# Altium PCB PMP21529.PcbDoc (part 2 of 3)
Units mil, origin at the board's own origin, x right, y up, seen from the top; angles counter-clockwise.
Board outline 4400 x 2200 mil, 4 copper layers (Top Layer, Signal Layer 1, Signal Layer 2, Bottom Layer), stack 41.2 mil thick; 196 components, 92 nets, 502 pads, 268 vias.
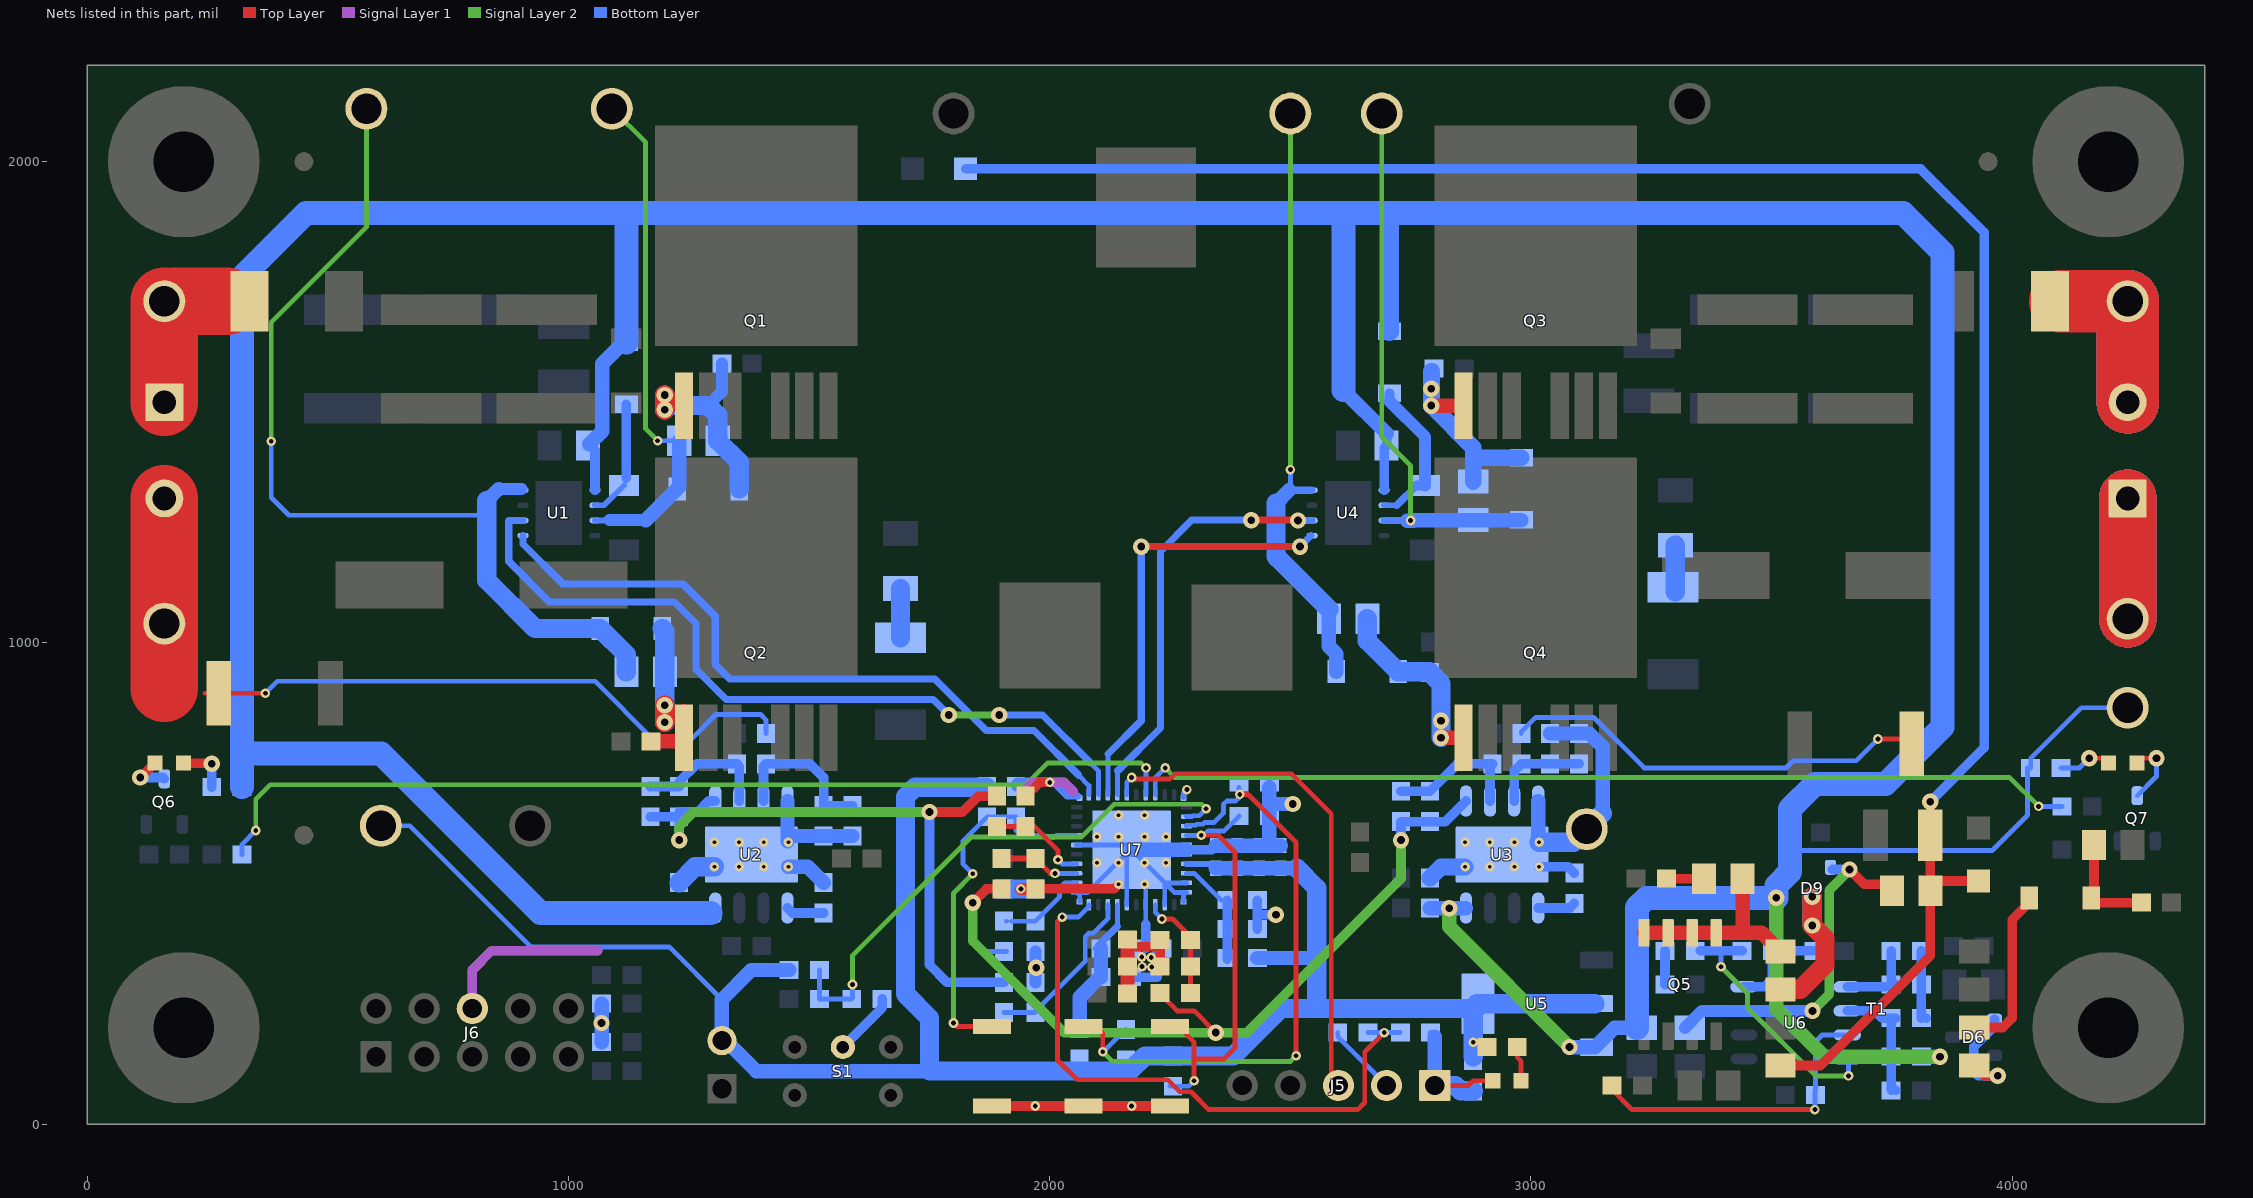
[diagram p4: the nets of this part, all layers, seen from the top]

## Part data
C1 C2 C3 C4 C5 C6 C7 C8: library part CMP-0009304-2, "CAP, CERM, 10 uF, 100 V, +/- 20%, X7R, 2220", Cap_Case=2220, Manufacturer=AVX, Supplier Part Number 1=478-9622-1-ND, TempCo=X7R, Tolerance_%=20%, Value1=Unknown, Value2=100V, ValueDisplayed=10uF
C9 C10: library part CMP-0011230-3, "CAP, AL, 100 uF, 100 V, +/- 20%, SMD", Cap_Case=KE0, Manufacturer=Chemi-Con, Tolerance_%=20%, Value1=Unknown, Value2=100V, ValueDisplayed=100uF
C11 C12: library part CMP-0007427-4, "CAP, CERM, 6800 pF, 25 V, +/- 10%, X7R, 0603", Cap_Case=0603, Manufacturer=MuRata, Supplier Part Number 1=81-GRM18R71E682KA01D, TempCo=X7R, Tolerance_%=10%, Value1=Unknown, Value2=25V, ValueDisplayed=6800pF
C13 C14 C21 C24 C27 C28: library part CMP-0006775-4, "CAP, CERM, 22 pF, 50 V, +/- 5%, C0G/NP0, 0603", Cap_Case=0603, Manufacturer=AVX, PartNumber=06035A220JAT2A, Supplier Part Number 1=478-1167-1-ND, TempCo=C0G/NP0, Tolerance_%=5%, Value1="0.259 ohm", Value2=50V, ValueDisplayed=22pF
C15 C16: library part CMP-0006752-5, "CAP, CERM, 0.1 uF, 25 V, +/- 5%, X7R, 0603", Cap_Case=0603, Manufacturer=AVX, PartNumber=06033C104JAT2A, Supplier Part Number 1=478-3713-1-ND, TempCo=X7R, Tolerance_%=5%, Value1="0.05 ohm", Value2=25V, ValueDisplayed=0.1uF
C17 C18: library part CMP-0006784-4, "CAP, CERM, 330 pF, 50 V, +/- 5%, C0G/NP0, 0603", Cap_Case=0603, Manufacturer=AVX, PartNumber=06035A331JAT2A, Supplier Part Number 1=478-1181-1-ND, TempCo=C0G/NP0, Tolerance_%=5%, Value1="0.071 ohm", Value2=50V, ValueDisplayed=330pF
C19 C29: library part CMP-0008334-2, "CAP, CERM, 4.7 uF, 16 V, +/- 10%, X7R, 0805", Cap_Case=0805, Manufacturer=MuRata, Supplier Part Number 1=490-4522-1-ND, TempCo=X7R, Tolerance_%=10%, Value1="0.006 ohm", Value2=16V, ValueDisplayed=4.7uF
C20 C22 C51: library part CMP-0006906-5, "CAP, CERM, 2.2 uF, 10 V, +/- 10%, X5R, 0603", Cap_Case=0603, Manufacturer=Kemet, PartNumber=C0603C225K8PACTU, Supplier Part Number 1=399-4911-1-ND, TempCo=X5R, Tolerance_%=10%, Value1=Unknown, Value2=10V, ValueDisplayed=2.2uF
C23 C30: library part CMP-0008724-2, "CAP, CERM, 2.2 uF, 100 V, +/- 10%, X7S, 1206", Cap_Case=1206_180, Manufacturer=TDK, Supplier Part Number 1=445-5207-1-ND, TempCo=X7S, Tolerance_%=10%, Value1="0.005718 ohm", Value2=100V, ValueDisplayed=2.2uF
C25 C66: library part CMP-0006895-4, "CAP, CERM, 220 pF, 50 V, +/- 10%, X7R, 0603", Cap_Case=0603, Manufacturer=Kemet, Supplier Part Number 1=399-1071-1-ND, TempCo=X7R, Tolerance_%=10%, Value1=Unknown, Value2=50V, ValueDisplayed=220pF
C26 C40 C47 C60: library part CMP-0006726-4, "CAP, CERM, 0.01 uF, 100 V, +/- 5%, X7R, 0603", Cap_Case=0603, Manufacturer=AVX, PartNumber=06031C103JAT2A, Supplier Part Number 1=478-3700-1-ND, TempCo=X7R, Tolerance_%=5%, Value1="0.098 ohm", Value2=100V, ValueDisplayed=0.01uF
C31 C34: library part CMP-0007770-2, "CAP, CERM, 2.2 uF, 16 V, +/- 10%, X7R, 0805", Cap_Case=0805, Manufacturer=Kemet, PartNumber=C0805C225K4RACTU, Supplier Part Number 1=399-3523-1-ND, TempCo=X7R, Tolerance_%=10%, Value1="0.008 ohm", Value2=16V, ValueDisplayed=2.2uF
C32: library part CMP-0007828-2, "CAP, CERM, 10 uF, 25 V, +/- 10%, X5R, 0805", Cap_Case=0805, Manufacturer=TDK, PartNumber=C2012X5R1E106K125AB, Supplier Part Number 1=445-5984-1-ND, TempCo=X5R, Tolerance_%=10%, Value1=Unknown, Value2=25V, ValueDisplayed=10uF
C33: library part CMP-0006872-5, "CAP, CERM, 10 uF, 6.3 V, +/- 20%, X5R, 0603", Cap_Case=0603, Manufacturer=Kemet, PartNumber=C0603C106M9PACTU, Supplier Part Number 1=399-5504-1-ND, TempCo=X5R, Tolerance_%=20%, Value1="0.004 ohm", Value2=6.3V, ValueDisplayed=10uF
C35: library part CMP-0009232-2, "CAP, CERM, 2.2 uF, 100 V, +/- 10%, X7R, 1210", Cap_Case=1210, Manufacturer=MuRata, Supplier Part Number 1=490-3385-1-ND, TempCo=X7R, Tolerance_%=10%, Value1="0.007 ohm", Value2=100V, ValueDisplayed=2.2uF
C36: library part CMP-0006854-4, "CAP, CERM, 0.01 uF, 50 V, +/- 10%, X7R, 0603", Cap_Case=0603, Manufacturer=Kemet, PartNumber=C0603C103K5RACTU, Supplier Part Number 1=399-1091-1-ND, TempCo=X7R, Tolerance_%=10%, Value1=Unknown, Value2=50V, ValueDisplayed=0.01uF
C37 C52: library part CMP-0007120-4, "CAP, CERM, 1 uF, 16 V, +/- 10%, X7R, 0603", Cap_Case=0603, Manufacturer="Taiyo Yuden", Supplier Part Number 1=1683647, TempCo=X7R, Tolerance_%=10%, Value1=Unknown, Value2=16V, ValueDisplayed=1uF
C38: library part CMP-0008244-2, "CAP, CERM, 47 pF, 250 V, +/- 5%, C0G/NP0, 0805", Cap_Case=0805, Manufacturer=MuRata, PartNumber=GRM21A5C2E470JW01D, Supplier Part Number 1=490-5538-1-ND, TempCo=C0G/NP0, Tolerance_%=5%, Value1=Unknown, Value2=250V, ValueDisplayed=47pF
C39: library part CMP-0006789-4, "CAP, CERM, 47 pF, 50 V, +/- 5%, C0G/NP0, 0603", Cap_Case=0603, Manufacturer=AVX, PartNumber=06035A470JAT2A, Supplier Part Number 1=478-1171-1-ND, TempCo=C0G/NP0, Tolerance_%=5%, Value1="0.174 ohm", Value2=50V, ValueDisplayed=47pF
C41: library part CMP-0006868-5, "CAP, CERM, 1 uF, 16 V, +/- 10%, X5R, 0603", Cap_Case=0603, Manufacturer=Kemet, PartNumber=C0603C105K4PACTU, Supplier Part Number 1=399-5090-1-ND, TempCo=X5R, Tolerance_%=10%, Value1=Unknown, Value2=16V, ValueDisplayed=1uF
C42 C43 C44: library part CMP-0006659-2, "CAP, CERM, 0.1 uF, 25 V, +/- 10%, X7R, 0402", Cap_Case=0402, Manufacturer=MuRata, Supplier Part Number 1=490-10698-1-ND, TempCo=X7R, Tolerance_%=10%, Value1=Unknown, Value2=25V, ValueDisplayed=0.1uF
C45: library part CMP-0064947-2, "CAP, CERM, 1 uF, 6.3 V,+/- 10%, X7R, 0402", Cap_Case=0402, Manufacturer=MuRata, Supplier Part Number 1=490-10024-1-ND, TempCo=X7R, Tolerance_%=10%, Value1=Unknown, Value2=6.3V, ValueDisplayed=1uF
C46: library part CMP-0006921-4, "CAP, CERM, 330 pF, 50 V, +/- 10%, X7R, 0603", Cap_Case=0603, Manufacturer=Kemet, PartNumber=C0603C331K5RACTU, Supplier Part Number 1=399-1073-1-ND, TempCo=X7R, Tolerance_%=10%, Value1=Unknown, Value2=50V, ValueDisplayed=330pF
C48: library part CMP-0006802-4, "CAP, CERM, 0.1 uF, 50 V, +/- 10%, X7R, 0603", Cap_Case=0603, Manufacturer=AVX, PartNumber=06035C104KAT2A, Supplier Part Number 1=478-5052-1-ND, TempCo=X7R, Tolerance_%=10%, Value1=Unknown, Value2=50V, ValueDisplayed=0.1uF
C49: library part CMP-0006895-4, "CAP, CERM, 220 pF, 50 V, +/- 10%, X7R, 0603", Cap_Case=0603, Manufacturer=Kemet, PartNumber=C0603C221K5RACTU, Supplier Part Number 1=399-1071-1-ND, TempCo=X7R, Tolerance_%=10%, Value1=Unknown, Value2=50V, ValueDisplayed=220pF
C50: library part CMP-0008334-2, "CAP, CERM, 4.7 uF, 16 V, +/- 10%, X7R, 0805", Cap_Case=0805, Manufacturer=MuRata, PartNumber=GRM21BR71C475KA73L, Supplier Part Number 1=490-4522-1-ND, TempCo=X7R, Tolerance_%=10%, Value1="0.006 ohm", Value2=16V, ValueDisplayed=4.7uF
C53: library part CMP-0006975-4, "CAP, CERM, 0.01 uF, 25 V, +/- 5%, C0G/NP0, 0603", Cap_Case=0603, Manufacturer=Kemet, Supplier Part Number 1=399-5779-1-ND, TempCo=C0G/NP0, Tolerance_%=5%, Value1=Unknown, Value2=25V, ValueDisplayed=0.01uF
C54 C56 C57: library part CMP-0064934-4, "CAP, CERM, 2.2 uF, 16 V,+/- 10%, X7R, 0603", Cap_Case=0603, Manufacturer="Taiyo Yuden", Supplier Part Number 1=587-4864-1-ND, TempCo=X7R, Tolerance_%=10%, Value1=Unknown, Value2=16V, ValueDisplayed=2.2uF
C55 C59: library part CMP-0006722-4, "CAP, CERM, 33 pF, 100 V, +/- 5%, C0G/NP0, 0603", Cap_Case=0603, Manufacturer=AVX, PartNumber=06031A330JAT2A, Supplier Part Number 1=478-1143-1-ND, TempCo=C0G/NP0, Tolerance_%=5%, Value1="0.209 ohm", Value2=100V, ValueDisplayed=33pF
C58 C64: library part CMP-0009182-2, "CAP, CERM, 4.7 uF, 100 V, +/- 10%, X7S, 1210", Cap_Case=1210, Manufacturer=MuRata, Supplier Part Number 1=81-GRM32DC72A475KE1L, TempCo=X7S, Tolerance_%=10%, Value1=Unknown, Value2=100V, ValueDisplayed=4.7uF
C61 C65: library part CMP-0008710-2, "CAP, CERM, 1 uF, 100 V, +/- 10%, X7R, 1206", Cap_Case=1206_180, Manufacturer=TDK, Supplier Part Number 1=445-4467-1-ND, TempCo=X7R, Tolerance_%=10%, Value1="0.004575 ohm", Value2=100V, ValueDisplayed=1uF
C62 C63: library part CMP-0008852-2, "CAP, CERM, 5600 pF, 100 V, +/- 5%, C0G/NP0, 1206", Cap_Case=1206, Manufacturer=MuRata, Supplier Part Number 1=490-3353-1-ND, TempCo=C0G/NP0, Tolerance_%=5%, Value1="0.005 ohm", Value2=100V, ValueDisplayed=5600pF
D1 D2 D3 D4: library part CMP-0028526-1, "Diode, Schottky, 40 V, 0.5 A, SOD-123", Manufacturer="ON Semiconductor", Supplier Part Number 1=MBR0540T1GOSCT-ND, Value1=0.5A, Value2=0.51V
D5 D7: library part CMP-0028782-1, "Diode, Schottky, 100 V, 1 A, AEC-Q101, SOD-123W", Manufacturer=Nexperia, Supplier Part Number 1=568-12693-1-ND, Value1=1A, Value2=0.77V
D6: library part CMP-0076887-1, "Diode, P-N, 100 V, 0.2 A, SOT-23", Manufacturer="Fairchild Semiconductor", PartNumber=MMBD914, Supplier Part Number 1=MMBD914FSCT-ND, Value1=0.2A, Value2=0.95V
D8: library part CMP-0028548-1, "Diode, Schottky, 40 V, 1 A, SOD-123FL", Manufacturer="ON Semiconductor", Supplier Part Number 1=MBR140SFT1GOSCT-ND, Value1=1A, Value2=0.55V
D9: library part CMP-0076885-1, "Diode, Switching, 70 V, 0.25 A, SOT-23", Manufacturer=Vishay-Semiconductor, PartNumber=BAW56-V-GS08, Supplier Part Number 1=BAW56-V-GS08CT-ND, Value1=0.25A, Value2=0V
D10 D11 D12: library part CMP-0002827-2, "LED, Green, SMD", Color=green, Manufacturer=Lite-On, Power_TotalModule=100mW, Supplier Part Number 1=160-1183-1-ND, Value1=0.1W, Value2=2.1V
D13 D14: library part CMP-0028625-1, "Diode, Schottky, 100 V, 1 A, SOD-123FL", Manufacturer="ON Semiconductor", Supplier Part Number 1=MBR1H100SFT3GOSCT-ND, Value1=1A, Value2=0.76V
F1 F2: library part CMP-0003604-2, "Fuse, 15 A, SMD", Irating_A=15A, Manufacturer="Bel Fuse", Supplier Part Number 1=507-1059-1-ND
FID1 FID2 FID3: library part CMP-0077181-1, "Fiducial mark.  There is nothing to buy or mount.", Manufacturer=N/A
H1 H2 H3 H4: library part CMP-0003617-1, "Machine Screw, Round, #4-40 x 1/4, Nylon, Philips panhead", Manufacturer="B&F Fastener Supply", Supplier Part Number 1=H542-ND
H5 H6 H7 H8: library part CMP-0003610-1, "Standoff, Hex, 0.5\"L #4-40 Nylon", Manufacturer=Keystone, Supplier Part Number 1=36-1902C-ND
J1 J3: library part CMP-0074910-1, "Terminal Block, 5.08 mm, 2x1, Brass, TH", Color=Blue, Current_A=15A, Manufacturer="On-Shore Technology", PartNumber=ED120/2DS, Supplier Part Number 1=ED1609-ND, Voltage_V=300V
J5: library part CMP-0075485-1, "Header, 100mil, 5x1, Gold, TH", Manufacturer=Samtec, Supplier Part Number 1=SAM8737-ND
J6: library part CMP-0054834-2, "Header (shrouded), 100mil, 5x2, Gold, TH", Manufacturer="TE Connectivity", PartNumber=5103308-1, Supplier Part Number 1=A33159-ND
J7: library part CMP-0075626-1, "Header, 100mil, 2x1, Gold, TH", Color=Black, Manufacturer=Samtec
L1: library part CMP-0061637-2, "Inductor, Shielded E Core, Ferrite, 15 uH, 21.9 A, 0.0026 ohm, SMD", Manufacturer=Coilcraft, Value1="0.0026 ohm", Value2=21.9A, ValueDisplayed=15uH
Logo3: library part CMP-0074847-1, "FCC_disclaimer"
NT1: library part CMP-0078142-1, "Single point connection between nets.", Manufacturer=N/A
Q1 Q2 Q3 Q4: library part CMP-0000920-1, "MOSFET, N-CH, 80 V, 180 A, AEC-Q101, DDPAK-7", Alternate Manufacturer=None, Manufacturer="Infineon Technologies", Supplier Part Number 1=726-IPB180N08S402ATM, Value2="128 nC"
Q5: library part CMP-0001082-1, "MOSFET, N-CH, 200 V, 3 A, SOIC-8", Alternate Manufacturer=None, Manufacturer="Fairchild Semiconductor", Supplier Part Number 1=FDS2670CT-ND, Value2="27 nC"
Q6 Q7: library part CMP-0000386-2, "Transistor, NPN, 40 V, 0.2 A, SOT-23", Manufacturer="Fairchild Semiconductor", Supplier Part Number 1=MMBT3904FSCT-ND, Value1="0.2 A", Value2=300
R1 R2: library part CMP-0024222-3, "RES, 41.2 k, 0.1%, 0.1 W, 0603", Manufacturer="Yageo America", Power_W=100mW, TempCo="25 ppm/C", Tolerance_%=0.1%, Value2=0.1W, Value_Code=41k2, ValueDisplayed=41.2k
R3 R4 R11 R12 R48 R54 R55: library part CMP-0021998-4, "RES, 10.0 k, 1%, 0.1 W, AEC-Q200 Grade 0, 0603", Manufacturer=Vishay-Dale, Power_W=100mW, Supplier Part Number 1=541-10.0KHCT-ND, TempCo="100 ppm/C", Tolerance_%=1%, Value2=0.1W, Value_Code=10k0, ValueDisplayed=10.0k
R5 R6 R7 R8: library part CMP-0021358-3, "RES, 5.11, 1%, 0.125 W, AEC-Q200 Grade 0, 0805", Manufacturer=Vishay-Dale, Power_W=125mW, Supplier Part Number 1=53K0318, TempCo="100 ppm/C", Tolerance_%=1%, Value2=0.125W, Value_Code=5R11, ValueDisplayed=5.11
R9 R10: library part CMP-0023875-3, "RES, 1.10 k, 0.1%, 0.1 W, 0603", Manufacturer="Yageo America", Power_W=100mW, TempCo="25 ppm/C", Tolerance_%=0.1%, Value2=0.1W, Value_Code=1k10, ValueDisplayed=1.10k
R13 R14: library part CMP-0015819-2, "RES, 0.002, 1%, 1 W, 2512", Manufacturer=Panasonic, PartNumber=ERJ-M1WTF2M0U, Power_W=1W, Supplier Part Number 1=P2.0NDCT-ND, TempCo=ppm/C, Tolerance_%=1%, Value_Code=2L000, ValueDisplayed=0.002
R15 R20: library part CMP-0025710-4, "RES, 120, 5%, 0.1 W, AEC-Q200 Grade 0, 0603", Manufacturer=Vishay-Dale, PartNumber=CRCW0603120RJNEA, Power_W=100mW, Supplier Part Number 1=541-120GCT-ND, TempCo="200 ppm/C", Tolerance_%=5%, Value2=0.1W, Value_Code=120R, ValueDisplayed=120
R16 R19 R25 R26: library part CMP-0022768-4, "RES, 120 k, 1%, 0.1 W, 0603", Manufacturer=Yageo, Power_W=100mW, Supplier Part Number 1=311-120KHRCT-ND, TempCo="100 ppm/C", Tolerance_%=1%, Value2=0.1W, Value_Code=120k
R17 R18 R21 R22 R34 R41 R49 R50: library part CMP-0022109-5, "RES, 1.00 k, 1%, 0.1 W, AEC-Q200 Grade 0, 0603", Manufacturer=Vishay-Dale, PartNumber=CRCW06031K00FKEA, Power_W=100mW, Supplier Part Number 1=541-1.00KHCT-ND, TempCo="100 ppm/C", Tolerance_%=1%, Value2=0.1W, Value_Code=1k00, ValueDisplayed=1.00k
R23 R24: library part CMP-0025729-4, "RES, 1.0 k, 5%, 0.1 W, AEC-Q200 Grade 0, 0603", Manufacturer=Vishay-Dale, PartNumber=CRCW06031K00JNEA, Power_W=100mW, Supplier Part Number 1=541-1.0KGCT-ND, TempCo="200 ppm/C", Tolerance_%=5%, Value2=0.1W, Value_Code=1k00, ValueDisplayed=1.0k
R28: library part CMP-0025047-3, "RES, 2.03 k, 0.5%, 0.1 W, 0603", Manufacturer="Yageo America", Power_W=100mW, TempCo="50 ppm/C", Tolerance_%=0.5%, Value2=0.1W, Value_Code=2k03, ValueDisplayed=2.03k
R29 R30: library part CMP-0022330-4, "RES, 31.6 k, 1%, 0.1 W, AEC-Q200 Grade 0, 0603", Manufacturer=Vishay-Dale, PartNumber=CRCW060331K6FKEA, Power_W=100mW, Supplier Part Number 1=541-31.6KHCT-ND, TempCo="100 ppm/C", Tolerance_%=1%, Value2=0.1W, Value_Code=31k6, ValueDisplayed=31.6k
R32: library part CMP-0023087-5, "RES, 3.74 k, 1%, 0.1 W, 0603", Manufacturer=Yageo, Power_W=100mW, Supplier Part Number 1=311-3.74KHRCT-ND, TempCo="100 ppm/C", Tolerance_%=1%, Value2=0.1W, Value_Code=3k74, ValueDisplayed=3.74k
R33: library part CMP-0021486-3, "RES, 90.9 k, 1%, 0.125 W, AEC-Q200 Grade 0, 0805", Manufacturer=Vishay-Dale, PartNumber=CRCW080590K9FKEA, Power_W=125mW, Supplier Part Number 1=541-90.9KCCT-ND, TempCo="100 ppm/C", Tolerance_%=1%, Value2=0.125W, Value_Code=90k9, ValueDisplayed=90.9k
R35: library part CMP-0022066-4, "RES, 15.0 k, 1%, 0.1 W, AEC-Q200 Grade 0, 0603", Manufacturer=Vishay-Dale, PartNumber=CRCW060315K0FKEA, Power_W=100mW, Supplier Part Number 1=541-15.0KHCT-ND, TempCo="100 ppm/C", Tolerance_%=1%, Value2=0.1W, Value_Code=15k0, ValueDisplayed=15.0k
R36 R37: library part CMP-0022220-4, "RES, 22.1 k, 1%, 0.1 W, AEC-Q200 Grade 0, 0603", Manufacturer=Vishay-Dale, PartNumber=CRCW060322K1FKEA, Power_W=100mW, Supplier Part Number 1=541-22.1KHCT-ND, TempCo="100 ppm/C", Tolerance_%=1%, Value2=0.1W, Value_Code=22k1, ValueDisplayed=22.1k
R38: library part CMP-0024910-2, "RES, 1.00, 0.5%, 0.1 W, 0603", Manufacturer="Yageo America", Power_W=100mW, TempCo="50 ppm/C", Tolerance_%=0.5%, Value2=0.1W, Value_Code=1R00, ValueDisplayed=1.00
R39: library part CMP-0022588-5, "RES, 750, 1%, 0.1 W, AEC-Q200 Grade 0, 0603", Manufacturer=Vishay-Dale, PartNumber=CRCW0603750RFKEA, Power_W=100mW, Supplier Part Number 1=541-750HCT-ND, TempCo="100 ppm/C", Tolerance_%=1%, Value2=0.1W, Value_Code=750R, ValueDisplayed=750
R40 R46 R47 R51: library part CMP-0021991-4, "RES, 100, 1%, 0.1 W, AEC-Q200 Grade 0, 0603", Manufacturer=Vishay-Dale, PartNumber=CRCW0603100RFKEA, Power_W=100mW, Supplier Part Number 1=541-100HCT-ND, TempCo="100 ppm/C", Tolerance_%=1%, Value2=0.1W, Value_Code=100R, ValueDisplayed=100
R42: library part CMP-0022454-4, "RES, 4.53 k, 1%, 0.1 W, AEC-Q200 Grade 0, 0603", Manufacturer=Vishay-Dale, Power_W=100mW, Supplier Part Number 1=541-4.53KHCT-ND, TempCo="100 ppm/C", Tolerance_%=1%, Value2=0.1W, Value_Code=4k53, ValueDisplayed=4.53k
R43: library part CMP-0022341-4, "RES, 33.2, 1%, 0.1 W, AEC-Q200 Grade 0, 0603", Manufacturer=Vishay-Dale, PartNumber=CRCW060333R2FKEA, Power_W=100mW, Supplier Part Number 1=541-33.2HCT-ND, TempCo="100 ppm/C", Tolerance_%=1%, Value2=0.1W, Value_Code=33R2, ValueDisplayed=33.2
R44: library part CMP-0021231-3, "RES, 3.01, 1%, 0.125 W, AEC-Q200 Grade 0, 0805", Manufacturer=Vishay-Dale, PartNumber=CRCW08053R01FKEA, Power_W=125mW, Supplier Part Number 1=541-3.01CCCT-ND, TempCo="100 ppm/C", Tolerance_%=1%, Value2=0.125W, Value_Code=3R01, ValueDisplayed=3.01
R45 R56 R57: library part CMP-0025769-4, "RES, 2.2 k, 5%, 0.1 W, AEC-Q200 Grade 0, 0603", Manufacturer=Vishay-Dale, Power_W=100mW, Supplier Part Number 1=541-2.2KGCT-ND, TempCo="200 ppm/C", Tolerance_%=5%, Value2=0.1W, Value_Code=2k20, ValueDisplayed=2.2k
R52 R53: library part CMP-0022373-4, "RES, 3.16 k, 1%, 0.1 W, AEC-Q200 Grade 0, 0603", Manufacturer=Vishay-Dale, Power_W=100mW, Supplier Part Number 1=541-3.16KHCT-ND, TempCo="100 ppm/C", Tolerance_%=1%, Value2=0.1W, Value_Code=3k16, ValueDisplayed=3.16k
R58 R59: library part CMP-0025750-4, "RES, 200 k, 5%, 0.1 W, AEC-Q200 Grade 0, 0603", Manufacturer=Vishay-Dale, Power_W=100mW, Supplier Part Number 1=541-200KGCT-ND, TempCo="200 ppm/C", Tolerance_%=5%, Value2=0.1W, Value_Code=200k
R60 R61: library part CMP-0016195-2, "RES, 3.3, 5%, 1 W, 2010", Manufacturer=Bourns, Power_W=1W, Supplier Part Number 1=652-CRM2010JW3R3ELF, TempCo="100 ppm/C", Tolerance_%=5%, Value_Code=3R30, ValueDisplayed=3.3
S1: library part CMP-0002136-2, "Switch, Toggle, SPDT 1Pos, TH", CurrentRating_mA=400A, Manufacturer="NKK Switches", Supplier Part Number 1=360-1758-ND
S2 S3 S4: library part CMP-0002113-2, "Switch, Push Button, SMD", CurrentRating_mA=50A, Manufacturer=Alps, Supplier Part Number 1=688-SKRKAE
T1: library part CMP-0030144-1, "Auxiliary Flyback Transformer, 540 uH, SMT", Manufacturer="XFMRS, Inc.", PartNumber=031-00019, ValueDisplayed=540uH
TP1 TP2 TP3 TP4 TP7 TP8 TP9 TP10 TP16 TP17: library part CMP-0055149-1, "Test Point, Multipurpose, White, TH", Color=White, Manufacturer=Keystone, Supplier Part Number 1=36-5012-ND
TP11 TP12 TP13 TP19: library part CMP-0055148-1, "Test Point, Multipurpose, Black, TH", Color=Black, Manufacturer=Keystone, Supplier Part Number 1=36-5011-ND
U1 U4: library part CMP-0066939-1, "120-V Boot, 4-A Peak, High Frequency High-Side and Low-Side Driver, DRM0008A (VSON-8)", Alternate Manufacturer="Texas Instruments", Alternate PartNumber=UCC27211ADRMT
U2 U3: library part CMP-0040615-2, "1.1 nV/rtHz Noise, Low Power, Precision Operational Amplifier, 4.5 to 36 V, -40 to 125 degC, 8-pin SOP (DDA8), Green (RoHS & no Sb/Br)", Manufacturer="Texas Instruments", Rating=Catalog, Total Supply Voltage(Max)(+5V is 5, +/-5V is 10)=36, Total Supply Voltage(Min)(+5V is 5, +/-5V is 10)=4.5
U5: library part CMP-0066030-1, "Single-Output LDO, 800mA, Fixed (3.3), Internal Current Limit, Thermal Overload Protection, DCY0004A (SOT-223-4)", Alternate Manufacturer="Texas Instruments"
U6: library part CMP-0067253-1, "Low Power Economy BiCMOS Current Mode PWM, D0008A (SOIC-8)", Alternate Manufacturer="Texas Instruments"
U7: library part CMP-0081542-1, "Highly Integrated Digital Controller for Isolated Power with 3 Feedback Loops and 8 DPWM Outputs, RJA0040A (VQFN-40)", Alternate Manufacturer="Texas Instruments", Alternate PartNumber=UCD3138RJAR, Operating Temprature Range="-40 to 125 C", Rating=Catalog
ZZ2: library part CMP-0077236-1
ZZ3: library part CMP-0077237-1
ZZ4: library part CMP-0077238-1

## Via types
v1: diameter 34, hole 16, Top Layer to Bottom Layer, 162 vias
v2: diameter 20, hole 10, Top Layer to Bottom Layer, 68 vias
v3: diameter 19.68, hole 7.87, Top Layer to Bottom Layer, 30 vias
v4: diameter 19.68, hole 7.87, Top Layer to Bottom Layer, tented both sides, 8 vias

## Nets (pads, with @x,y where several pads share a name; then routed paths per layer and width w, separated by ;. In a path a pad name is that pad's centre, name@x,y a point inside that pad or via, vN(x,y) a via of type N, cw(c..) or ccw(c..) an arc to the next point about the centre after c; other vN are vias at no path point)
3.3VA: C40.1 C41.1 R38.2 U7.37 | length 291.6
  Bottom Layer w10: C40.1@2093.5,365 C40.1@2095.28,365 ; C40.1@2103.5,365 C40.1@2103.5,373.5 ; 2140.47,410.47 U7.37@2140.47,455.83
  Bottom Layer w15: C40.1@2103.5,373.5 2140.47,410.47
  Bottom Layer w30: R38.2@2062,198.5 2062,263.5 C41.1@2103.5,305 ; C41.1@2106.5,305 C40.1@2106.5,365
3.3VD: C33.1 C42.1 C43.1 C44.1 C45.1 C51.2 J7.2 R34.1 R38.1 R45.2 R48.2 R56.2 R57.2 TP16.1 U5.2 U5.4 U7.27 | length 4572.1
  Top Layer w10: v2(2880,170) 2898.5,170 R34.1@2908.5,160
  Bottom Layer w10: TP16.1@610,620 670,620 922.46,367.54 1210,367.54 1318.77,258.77
  Bottom Layer w12: U7.27@2284.17,540.47 C42.1@2340.91,540.47
  Bottom Layer w20: J7.2@1318.77,173.39 J7.2@1326.61,173.39 ; U5.4@2880,243.03 U5.4@2886.97,250
  Bottom Layer w30: J7.2@1318.77,173.39 1318.77,258.77 1380,320 R48.2@1458.5,320 ; J7.2@1326.61,173.39 1390,110 1750,110 ; R45.2@1868.5,700 R45.2@1870,701.5 ; C42.1@2345,531.38 C43.1@2390,531.38 C44.1@2435,531.38 C45.1@2480,531.38 2513.62,531.38 ; C51.2@2431.5,345 2555,345
  Bottom Layer w40: R45.2@1868.5,700 1720,700 1700,680 1700,270 1750,220 1750,110 2166.31,110 2197.81,141.5 ; 2201.5,141.5 2250,141.5 2381.5,141.5 2480,240 2555,240 ; 2513.62,531.38 2555,490 2555,240 ; C33.1@2880,140 U5.4@2880,243.03 ; U5.4@2886.97,240 2555,240 ; U5.4@2886.97,250 U5.2@3133.03,250
6V: C34.1 D8.1 R59.2 | length 226.3
  Top Layer w20: C34.1@4170,580 4170,465.53 4164.47,460 R59.2@4268.5,460
12V: C15.1 C16.1 C19.1 C29.1 C32.1 C37.1 D9.1 D13.2 D14.2 R35.1 R49.1 R50.1 TP17.1 U1.1 U2.8 U3.8 U4.1 U5.3 | length 11560
  Signal Layer 2 w30: v1(2830,448.5) 2830,410 v1(3080,160) ; v1(3510,470) 3510,240 3610,140 v1(3850,140)
  Bottom Layer w10: 3538.5,570 3540.38,568.13 3958.13,568.13 4032.13,642.13 R50.1@4032.13,740 ; R50.1@4038.5,740 4038.5,760 4143.5,865 TP17.1@4240,865
  Bottom Layer w12: C29.1@2694.8,1404.8 C29.1@2700,1410
  Bottom Layer w20: C19.1@1042.5,1412.5 1054.8,1400.2 U1.1@1054.8,1317.24 ; U2.8@1294.72,438.5 U2.8@1305,448.78 ; U4.1@2694.8,1317.24 C29.1@2694.8,1404.8 ; C29.1@2700,1410 C29.1@2700,1435 ; U3.8@2864.72,448.5 U3.8@2865,448.78 ; v1@3079.45,159.45 v1(3080,160) ; R35.1@3811.5,140 v1(3850,140)
  Bottom Layer w30: C19.1@1042.5,1412.5 1070,1440 1070,1580 1114.47,1624.47 D13.2@1120,1624.47 ; 2610,1525 C29.1@2700,1435 ; C16.1@2790,448.5 v1(2830,448.5) U3.8@2864.72,448.5 ; v1@3079.45,159.45 3133.03,159.45 3173.58,200 C32.1@3230,200
  Bottom Layer w40: D14.2@2706,1647.47 2706,1888
  Bottom Layer w50: R49.1@321.5,700 321.5,1760.5 454,1893 3773,1893 3855,1811 3855,825 3736.5,706.5 3590,706.5 3538.5,655 C37.1@3538.5,606 3538.5,570 3538.5,524.21 3510,495.71 v1(3510,470) 3240,470 3220,450 C32.1@3220,200 ; 326.5,770 610,770 941.5,438.5 C15.1@1230,438.5 U2.8@1294.72,438.5 ; D13.2@1120,1624.47 1120,1889 ; 2610,1525 2610,1891
AGND: C11.2 C12.2 C15.2 C16.2 C17.2 C18.2 C20.2 C21.2 C22.2 C24.2 C25.2 C26.2 C27.2 C28.2 C33.2 C40.2 C41.2 C42.2 C43.2 C44.2 C45.2 C47.2 C52.2 C53.2 C54.2 C55.2 C56.2 C57.2 C59.2 C60.2 C66.2 D10.2 J5.1 J6.6 NT1.2 R9.1 R10.1 R25.1 R26.1 R32.1 S1.5 S2.1 S3.1 S4.1 TP19.1 U2.4 U2.9@1380,560 U3.4 U3.9@2940,560 U7.1 U7.6 U7.25 U7.26 U7.29 U7.30 U7.32 U7.34 U7.36 U7.41@2170,570 U7.A1 U7.A2 U7.A3 U7.A4 | length 4864
  Top Layer w10: J5.1@2800,80 2870,80 2880,90 D10.2@2920.47,90
  Top Layer w20: S2.1@1880,37.32 S3.1@2070,37.32 S4.1@2250,37.32 ; C17.2@1950,681.5 1978.5,710 v2(2000,710) ; C18.2@1970,488.5 2133.39,488.5 v3(2143.03,498.15) ; C66.2@2163.5,368 C26.2@2226.5,368 ; R32.1@2229.5,329 C26.2@2229.5,389
  Top Layer w25: v2(1940,488.5) C18.2@1970,488.5
  Top Layer w30: R10.1@2161.5,271 C66.2@2161.5,383
  Signal Layer 1 w20: J6.6@800,240 800,320 840,360 1060,360 ; 1940,684.45 1965.55,710 v2(2000,710) 2030,710 2048.94,691.06
  Bottom Layer w10: S1.5@1570,160 S1.5@1590,160 ; U7.6@2055.83,579.84 2160.16,579.84 U7.41@2170,570 2167.68,570 2079.09,481.42 U7.1@2055.83,481.42 2062.13,475.12 U7.A1@2062.13,462.13 ; U7.36@2160.16,455.83 U7.41@2160.16,560.16 ; v3(2196.97,498.15) 2199.53,495.59 U7.34@2199.53,455.83 2199.53,415.47 ; U7.32@2238.9,455.83 2238.9,498.9 U7.41@2240,500 ; U7.A4@2277.87,462.13 2277.87,475.12 U7.30@2284.17,481.42 2258.58,481.42 U7.41@2240,500 ; U7.A3@2277.87,677.87 2277.87,687.87 v2(2285,695) ; U7.29@2284.17,501.1 2241.1,501.1 U7.41@2240,500 ; 2284.17,570 U7.26@2284.17,560.16 2179.84,560.16 v3(2196.97,543.03) U7.41@2240,500 ; C56.2@2456.5,710 C56.2@2456.5,723.5 ; C47.2@2791.5,190 C47.2@2800,181.5
  Bottom Layer w15: v2(2000,710) 2007.94,710 2036.44,681.5 2058.5,681.5 U7.A2@2058.54,681.46
  Bottom Layer w20: U2.9@1455,587.36 v4(1456.77,585.59) U2.9@1469.69,598.5 ; S1.5@1570,160 1651.5,241.5 C60.2@1651.5,260 ; C54.2@1930,701.5 C54.2@1930,707.87 ; C54.2@1932.13,710 v2(2000,710) ; C41.2@2166.5,305 C41.2@2169.5,305 2223.5,305 2223.5,365 C25.2@2223.5,368.5 ; 2199.53,365.47 2199.53,415.47 ; 2284.17,570 2336.38,570 C42.2@2345,578.62 ; C52.2@2431.5,405 C53.2@2431.5,465 ; 2434.23,435 v1(2470,435) ; U3.9@3015,587.36 v4(3016.77,585.59) ; v4(3016.77,534.41) 3077.09,534.41 C27.2@3090,521.5
  Bottom Layer w25: C20.2@1970,294.5 C22.2@1970,358.5
  Bottom Layer w30: C59.2@1068.5,170 C55.2@1068.5,250 ; U2.9@1455,587.36 U2.4@1455,671.22 ; v4(1456.77,534.41) 1497.09,534.41 C28.2@1530,501.5 ; U2.9@1469.69,598.5 C21.2@1590,598.5 ; U7.41@2170,570 2284.17,570 ; C42.2@2345,578.62 C43.2@2390,578.62 C44.2@2435,578.62 C45.2@2480,578.62 ; 2456.5,581.63 C57.2@2456.5,640 C56.2@2456.5,700 ; 2458.77,665 v1(2505,665) ; J5.1@2800,80 C47.2@2800,181.5 ; U3.9@3015,587.36 U3.4@3015,671.22 ; C24.2@3040,811.5 R26.1@3100,811.5 3121.06,811.5 3148.78,783.78 3148.78,645.78
  Bottom Layer w35: C16.2@2790,511.5 2812.91,534.41 v4(2863.23,534.41)
  Bottom Layer w40: C15.2@1230,501.5 1262.91,534.41 v4(1303.23,534.41) ; R9.1@1910,488.5 v2(1940,488.5) C11.2@1970,488.5 ; J5.1@2800,80 2842.48,80 2853.98,68.5 C33.2@2880,68.5 ; v4(3016.77,585.59) 3088.59,585.59 TP19.1@3116,613 3148.78,645.78
  other v1: 1068.5,210 1972,325
  other v2: 1970,37.32 2170,37.32 2212,326 2192,327 2211,346 2191,347
  other v3: 1354.41,534.41 1405.59,534.41 2914.41,534.41 2965.59,534.41 2098.15,543.03 2143.03,543.03 2241.85,543.03 1354.41,585.59 1405.59,585.59 2914.41,585.59 2965.59,585.59 2098.15,596.97 2143.03,596.97 2196.97,596.97 2241.85,596.97 2143.03,641.85 2196.97,641.85
  other v4: 1303.23,585.59 2863.23,585.59
CBC1: C17.1 R15.2 U7.4 | length 209.9
  Top Layer w10: R15.2@1890,618.5 C17.1@1950,618.5 1967.5,618.5 2017,569 v2(2017,549)
  Bottom Layer w10: v2(2017,549) 2025.53,540.47 U7.4@2055.83,540.47
CBC2: C18.1 R20.2 U7.3 | length 158.5
  Top Layer w10: C18.1@1970,551.5 2000.71,520.79 v2(2010.79,520.79)
  Top Layer w12: R20.2@1910,551.5 C18.1@1970,551.5
  Bottom Layer w10: v2(2010.79,520.79) U7.3@2055.83,520.79
CHARGE_V1: R52.1 U7.17 | length 2068
  Signal Layer 2 w10: v2(350,610) 350,675 380,705 1950.13,705.13 1995,750 2190,750 v2(2200,740)
  Bottom Layer w10: R52.1@321.5,560 321.5,581.5 v2(350,610) ; U7.17@2199.53,684.17 2200,684.65 v2(2200,740)
CHARGE_V2: R53.1 U7.18 | length 1961.1
  Signal Layer 2 w10: v2(2240,740) 2260,720 3995,720 v2(4055,660)
  Bottom Layer w10: U7.18@2219.21,684.17 2219.21,719.21 v2(2240,740) ; v2(4055,660) R53.1@4103.5,660
DIRECTION: C60.1 R48.1 R51.2 U7.22 | length 1128.4
  Signal Layer 2 w10: v2(1590,290) 1590,350 1836.34,596.34 2065.39,596.34 2133.62,664.57 2315.43,664.57 v2(2325,655)
  Bottom Layer w10: R48.1@1521.5,320 1521.5,300 R51.2@1521.5,260 C60.1@1588.5,260 1590,261.5 v2(1590,290) ; U7.22@2284.17,638.9 2296.27,638.9 2296.27,640.75 2310.75,640.75 v2@2320,650
DPWM0A: U1.5 U7.11 | length 1479.4
  Bottom Layer w10: 2060,724.72 2081.42,703.31 U7.11@2081.42,684.17
  Bottom Layer w15: U1.5@905.2,1222.76 905.2,1205.2 987.89,1122.5 1237.5,1122.5 1305,1055 1305,955 1335,925 1760.78,925 1868.16,817.63 1967.1,817.63 2060,724.72
DPWM0B: U1.6 U7.12 | length 1625.5
  Signal Layer 2 w15: v1(1790,850) v1(1895,850)
  Bottom Layer w10: 2085,750 2101.1,733.9 U7.12@2101.1,684.17
  Bottom Layer w15: U1.6@905.2,1254.25 875.75,1254.25 875.75,1169.25 960,1085 1220,1085 1265,1040 1265,945 1327.63,882.37 1757.63,882.37 v1(1790,850) ; v1(1895,850) 1985,850 2085,750
DPWM1A: U4.5 U7.13 | length 909.1
  Top Layer w15: v1(2190,1200) v1(2520,1200)
  Bottom Layer w10: U7.13@2120.79,684.17 2120.79,769 ; U4.5@2542.76,1222.76 U4.5@2545.2,1222.76
  Bottom Layer w15: 2120.79,769 2190,838.21 v1(2190,1200) ; v1(2520,1200) U4.5@2542.76,1222.76
DPWM1B: U4.6 U7.14 | length 898.9
  Top Layer w10: v1@2511.5,1250 v1(2515.75,1254.25)
  Top Layer w15: v1(2419,1255) 2515,1255 v1(2515.75,1254.25)
  Signal Layer 2 w10: v1@2515.75,1245.75 v1(2515.75,1254.25)
  Bottom Layer w10: U7.14@2140.47,684.17 2140.47,733.47
  Bottom Layer w15: 2141.16,734.16 2230,823 2230,1190 2295,1255 v1(2419,1255) ; v1(2515.75,1254.25) U4.6@2545.2,1254.25
DPWM2A: J5.3 U7.15 | length 1066.3
  Top Layer w10: v2(2170,720) 2172.87,717.13 2249.47,717.13 2260.35,728 2502.16,728 2530,700.16 2530,700 2585,645 2585,95 J5.3@2600,80
  Bottom Layer w10: U7.15@2160.16,684.17 2160.16,710.16 v2(2170,720)
H1: D1.1 R5.1 TP9.1 U1.3 | length 1074.2
  Signal Layer 2 w10: TP9.1@1090,2110 1160,2040 1160,1445 v2(1185,1420)
  Bottom Layer w10: v2(1185,1420) R5.1@1230,1420
  Bottom Layer w12: U1.3@1054.8,1254.25 1084.25,1254.25 ; D1.1@1225.53,1320 D1.1@1230,1324.47
  Bottom Layer w20: 1084.25,1254.25 1085,1255
  Bottom Layer w25: 1085,1255 1160.53,1255
  Bottom Layer w30: 1160.53,1255 D1.1@1225.53,1320 ; D1.1@1230,1324.47 R5.1@1230,1420
H2: D4.1 R8.2 TP8.1 U4.3 | length 1160.6
  Signal Layer 2 w10: TP8.1@2690,2100 2690,1428 2750,1368 v2(2750,1254.25)
  Bottom Layer w15: U4.3@2694.8,1254.25 2736.38,1254.25 ; R8.2@2884.25,1254.25 R8.2@2885,1255
  Bottom Layer w30: v2@2743,1254 v2@2756.62,1254 ; v2(2750,1254.25) R8.2@2884.25,1254.25 ; R8.2@2880,1255 2885,1255 D4.1@2979.47,1255
I_Share: C47.1 R40.1 U7.40 | length 1288.8
  Top Layer w10: v2(2026,430) 2016.13,420.13 2016.13,132.87 2057,92 2245,92 2269.87,67.13 2293.52,67.13 2330.65,30 2640,30 2654.65,44.65 2654.65,149.65 v2(2695,190)
  Bottom Layer w10: v2@2028,432 v2(2026,430) 2059.66,430 2081.42,451.76 U7.40@2081.42,455.83 ; R40.1@2661.5,190 v2(2695,190) C47.1@2728.5,190
Iout1: C20.1 R23.2 U7.38 | length 357.1
  Bottom Layer w10: R23.2@1905,231.5 C20.1@1970,231.5 1970,234 2073.94,337.94 2073.94,389.03 2081.49,396.57 2090.57,396.57 2120.79,426.79 U7.38@2120.79,455.83
Iout2: C22.1 R24.2 U7.2 | length 189.6
  Bottom Layer w10: R24.2@1920,421.5 C22.1@1960,421.5 ; 1950,421.5 C22.1@1970,421.5 2020,471.5 2020,490 2031.1,501.1 U7.2@2055.83,501.1
Iout2_sense: C26.1 R28.1 R32.2 U7.33 | length 231.8
  Top Layer w10: v2(2233,426) 2255.5,426 2292.5,389 R28.1@2292.5,270
  Bottom Layer w10: U7.33@2219.21,455.83 2219.21,439.79 v2(2233,426) 2234,426 v2@2235,425
L1: D2.1 R6.1 TP10.1 U1.8 | length 1990.1
  Signal Layer 2 w10: v2(382,1419) 382,1666 580,1864 TP10.1@580,2110
  Bottom Layer w10: v2(382,1419) 382,1302 419,1265 830,1265
  Bottom Layer w25: 854.53,1319.53 U1.8@902.13,1319.53
  Bottom Layer w30: 830,1295 854.53,1319.53
  Bottom Layer w40: 830,1295 830,1265 830,1130 930,1030 D2.1@1065.53,1030 1120,975.53 R6.1@1120,940
L2: D3.1 R7.2 TP7.1 U4.8 | length 1278.4
  Signal Layer 2 w10: v2(2500,1360) TP7.1@2500,2100
  Bottom Layer w10: 2497.24,1317.24 2500,1320 v2(2500,1360)
  Bottom Layer w15: 2497.24,1317.24 U4.8@2545.2,1317.24
  Bottom Layer w20: R7.2@2580,1050 R7.2@2580,1070 ; D3.1@2595.53,940 D3.1@2600,944.47
  Bottom Layer w30: 2470.37,1290.37 2497.24,1317.24 ; R7.2@2580,1050 2580,993 2595.53,977.47 D3.1@2595.53,940
  Bottom Layer w40: 2470.37,1290.37 2470.37,1179.63 2480,1170 R7.2@2580,1070
NetC13_1: C13.1 R16.2 R21.2 U2.2 | length 274.7
  Bottom Layer w20: R16.2@1170,701.5 C13.1@1230,701.5 ; C13.1@1230,711.5 1267.01,748.5 R21.2@1350,748.5 1355,743.5 U2.2@1355,671.22
NetC13_2: C13.2 R15.1 R16.1 R23.1 U2.1 | length 1395.1
  Top Layer w20: v1(1750,648.5) 1818.5,648.5 1851.5,681.5 R15.1@1890,681.5
  Signal Layer 2 w20: v1(1230,590) 1230,618.5 1260,648.5 v1(1750,648.5)
  Bottom Layer w20: R16.1@1170,638.5 C13.2@1230,638.5 v1(1230,590) ; C13.2@1230,648.5 1268.5,648.5 1291.22,671.22 U2.1@1305,671.22 ; v1(1750,648.5) 1750,420 1750,331 1786.5,294.5 R23.1@1905,294.5
NetC14_1: C14.1 R19.1 R22.2 U3.2 | length 293
  Bottom Layer w20: R19.1@2730,691.5 C14.1@2790,691.5 2847.01,748.5 R22.2@2920,748.5 2915,743.5 U3.2@2915,671.22
NetC14_2: C14.2 R19.2 R20.1 R24.1 R28.2 U3.1 | length 1821.8
  Top Layer w10: R28.2@2229.5,270 2264.5,235 2300,235 v1(2345,190)
  Top Layer w20: v1(1840,460) 1868.5,488.5 R20.1@1900,488.5
  Signal Layer 2 w20: v1(1840,460) 1840,380 2030,190 v1(2345,190) 2410,190 2730,510 v1(2730,590)
  Bottom Layer w10: v1@1840,450 1840,380 1861.5,358.5 R24.1@1910,358.5
  Bottom Layer w20: v1(2730,590) R19.2@2730,628.5 C14.2@2790,628.5 2822.28,628.5 U3.1@2865,671.22
NetC21_1: C21.1 R17.2 R25.2 U2.3 | length 329.7
  Bottom Layer w20: U2.3@1405,671.22 1405,743.5 R17.2@1410,748.5 1501.5,748.5 1530,720 R25.2@1530,661.5 C21.1@1590,661.5
NetC23_1: C23.1 D13.1 U1.2 | length 230.9
  Bottom Layer w12: U1.2@1054.8,1285.75 1073.82,1285.75 C23.1@1115,1326.93
  Bottom Layer w20: C23.1@1120,1341.93 D13.1@1120,1495.53
NetC24_1: C24.1 R18.2 R26.2 U3.3 | length 203.5
  Bottom Layer w20: U3.3@2965,671.22 2965,733.5 R18.2@2980,748.5 R26.2@3100,748.5
NetC27_1: C27.1 U3.5 | length 79
  Bottom Layer w20: U3.5@3015,448.78 3080.28,448.78 C27.1@3090,458.5
NetC28_1: C28.1 U2.5 | length 79.3
  Bottom Layer w20: U2.5@1455,448.78 1465.28,438.5 C28.1@1530,438.5
NetC30_1: C30.1 D14.1 U4.2 | length 324.5
  Bottom Layer w12: U4.2@2694.8,1285.75 2721.25,1285.75
  Bottom Layer w15: 2721.25,1285.75 C30.1@2762.43,1326.93
  Bottom Layer w20: D14.1@2706,1502 D14.1@2706,1518.53 ; C30.1@2762.43,1326.93 C30.1@2780,1326.93
  Bottom Layer w25: D14.1@2706,1502 2780,1428 C30.1@2780,1326.93
NetC35_1: C35.1 D5.1 D7.1 R33.1 T1.4 | length 4240.3
  Top Layer w20: T1.4@3518.5,121.5 3601.5,121.5 3830,350 R33.1@3830,485 ; v1(3830,670) R33.1@3830,485 ; D7.1@3930,504.88 3849.88,504.88 R33.1@3830,485
  Signal Layer 1 w20: v1(3830,670) v1@3835,670
  Bottom Layer w20: D5.1@1825.12,1985 3810,1985 3942,1853 3942,782 v1(3830,670)
NetC36_1: C36.1 R35.2 R42.2 U6.2 | length 257.4
  Bottom Layer w20: U6.2@3657.28,235 3715,235 3730,220 C36.1@3758.5,220 ; R42.2@3748.5,70 R35.2@3748.5,140 C36.1@3748.5,220
NetC36_2: C36.2 C39.1 R36.1 | length 140
  Bottom Layer w20: C36.2@3811.5,220 C39.1@3811.5,290 R36.1@3811.5,360
NetC38_1: C38.1 Q5.5 Q5.6 Q5.7 Q5.8 T1.1 | length 412.3
  Top Layer w30: Q5.8@3235,397.28 Q5.7@3285,397.28 Q5.6@3335,397.28 Q5.5@3385,397.28 3479.72,397.28 T1.1@3518.5,358.5 ; 3440,397.28 C38.1@3440,510
NetC38_2: C38.2 R39.1 | length 78.5
  Top Layer w20: R39.1@3281.5,510 C38.2@3360,510
NetC39_2: C39.2 R36.2 U6.1 | length 173.3
  Bottom Layer w20: U6.1@3657.28,285 3753.5,285 C39.2@3758.5,290 ; C39.2@3748.5,290 R36.2@3748.5,360
NetC46_1: C46.1 R43.1 | length 70
  Bottom Layer w20: R43.1@3278.5,290 C46.1@3278.5,360
NetC46_2: C46.2 R37.2 U6.4 | length 533
  Signal Layer 2 w10: v2(3395,326.74) 3450,271.74 3450,241.5 3591.5,100 v2(3660,100)
  Bottom Layer w10: v2(3395,326.74) 3395,360 ; v2(3660,100) U6.4@3660,132.28
  Bottom Layer w20: C46.2@3351.5,360 3395,360 R37.2@3438.5,360 ; U6.4@3657.28,135 U6.4@3660,132.28
NetC48_1: C48.1 R37.1 U6.8 | length 211.1
  Bottom Layer w20: U6.8@3442.72,285 3485,285 3501.5,301.5 R37.1@3501.5,360 C48.1@3588.5,360
NetC49_1: C49.1 R41.2 U6.3 | length 660.7
  Top Layer w10: R41.2@3168.5,80 3168.5,71.5 3210,30 v2(3590,30)
  Bottom Layer w10: v2(3590,30) 3590,68.5 3591.5,70 3591.5,171.5 3605,185 U6.3@3657.28,185
NetC50_1: C50.1 D9.2 R33.2 U6.7 | length 746.9
  Top Layer w20: v1(3662,529) 3693,498 3737,498 R33.2@3750,485
  Signal Layer 2 w20: v1(3585,235) 3620,270 3620,486 3662,528 v1(3662,529)
  Bottom Layer w20: D9.2@3626.71,529 v1(3662,529)
  Bottom Layer w25: C50.1@3320,200 3355,235 U6.7@3442.72,235 v1(3585,235)
NetC51_1: C51.1 C52.1 C53.1 U7.28 | length 222.4
  Bottom Layer w10: U7.28@2284.17,520.79 2300.21,520.79 2356,465 C53.1@2368.5,465
  Bottom Layer w20: C51.1@2368.5,342 C52.1@2368.5,397 ; C52.1@2368.5,405 C53.1@2368.5,465
NetC54_1: C54.1 R45.1 S2.2 U7.7 | length 778.4
  Top Layer w10: v2(1800,210) 1807.32,202.68 S2.2@1880,202.68
  Signal Layer 2 w10: v2(1800,210) 1800,480 v2(1840,520)
  Bottom Layer w10: v2(1840,520) 1820,540 1820,588.5 R45.1@1870,638.5 C54.1@1930,638.5 1930,610 1940.47,599.53 1988.12,599.53 1991.31,596.34 2010.26,596.34 2013.45,599.53 U7.7@2055.83,599.53
NetC56_1: C56.1 R56.1 S3.2 U7.23 | length 1336.2
  Top Layer w10: S3.2@2070,202.68 2097.32,202.68 2110,190 v2(2110,150) ; v2(2395,685) 2412,685 2512,585 v2(2512,142)
  Signal Layer 2 w10: v2(2110,150) 2130,130 2500,130 v2(2512,142)
  Bottom Layer w10: v2(2110,150) 2111.5,150 R56.1@2158,196.5 ; U7.23@2284.17,619.21 2284.17,621.02 2303.68,621.02 2305.53,622.87 2318.15,622.87 2322.15,626.87 2341.87,626.87 2360.94,645.94 2360.94,664.03 2368.49,671.57 2386.57,671.57 2393.5,678.5 C56.1@2393.5,700
NetC57_1: C57.1 R57.1 S4.2 U7.24 | length 909.6
  Top Layer w10: S4.2@2250,202.68 2267.32,202.68 2300,170 2300,135 ; v2(2300,90) 2300,135 ; v2(2315,600) 2349.72,600 2385,564.72 2385,158 2362,135 2300,135
  Bottom Layer w10: R57.1@2250,78.5 2288.5,78.5 v2(2300,90) ; U7.24@2284.17,599.53 v2@2314.53,599.53 ; v2(2315,600) 2320.61,600 2329.61,609 2362.5,609 C57.1@2393.5,640
NetC62_2: C62.2 R60.2 | length 102.4
  Bottom Layer w40: R60.2@1690,1010.55 C62.2@1690,1112.91
NetC63_2: C63.2 R61.2 | length 97.4
  Bottom Layer w40: R61.2@3300,1105.55 C63.2@3300,1202.91
NetD1_2: D1.2 Q1.1 R3.1 R5.2 | length 458.3
  Top Layer w40: v1(1200,1484.37) v1(1200,1515) ; v1@1207,1500 Q1.1@1225,1500
  Bottom Layer w25: 1290,1493 1318.5,1521.5 R3.1@1318.5,1580
  Bottom Layer w40: v1(1200,1484.37) v1(1200,1515) ; v1@1209.5,1493 1290,1493 1310,1473 R5.2@1310,1420 1354.47,1375.53 D1.2@1354.47,1320
NetD2_2: D2.2 Q2.1 R6.2 R11.2 | length 390.3
  Top Layer w25: Q2.1@1230,850 1240,860 Q2.1@1240,803
  Top Layer w30: R11.2@1171.5,795 Q2.1@1232,795
  Top Layer w40: v1(1200,835) v1@1200,850 ; v1(1200,870) v1@1200,850 ; Q2.1@1230,850 v1@1200,850
  Bottom Layer w25: R6.2@1195.53,934.47 R6.2@1200,930
  Bottom Layer w40: D2.2@1194.47,1030 1200,1024.47 R6.2@1200,940 ; v1(1200,835) v1(1200,870) R6.2@1200,930
NetD3_2: D3.2 Q4.1 R7.1 R12.2 | length 392.8
  Top Layer w30: v1(2813,803) Q4.1@2860,803
  Bottom Layer w40: R7.1@2660,1050 2660,1004.47 D3.2@2724.47,940 R12.2@2788.5,940 ; R12.2@2790,938.5 2813,915.5 v1(2813,803)
  other v1: 2813,838
NetD4_2: D4.2 Q3.1 R4.1 R8.1 | length 434.8
  Top Layer w30: v1(2793,1493) Q3.1@2860,1493
  Bottom Layer w20: R4.1@2793,1564.5 R4.1@2798.5,1570
  Bottom Layer w35: R4.1@2793,1564.5 v1(2793,1493) 2880,1406 R8.1@2880,1335 ; 2885.53,1384.47 D4.2@2980,1384.47
  other v1: 2793,1528
NetD6_1: D6.1 T1.5 | length 236.9
  Top Layer w20: T1.5@3921.5,121.5 3943,100 v1(3970,100)
  Bottom Layer w20: D6.1@3963.31,217.4 3963.31,203.31 3920,160 3920,110 3930,100 v1(3970,100)
NetD8_2: D8.2 T1.6 | length 341.3
  Top Layer w20: T1.6@3921.5,200.5 3980.5,200.5 4000,220 4000,424.47 D8.2@4035.53,460
NetD9_3: D9.3 T1.2 | length 326.4
  Top Layer w30: T1.2@3518.5,279.5 T1.2@3519,280
  Top Layer w40: T1.2@3519,280 3560.14,280 3595,314.86 3595,315 3611,331 3611,386 v1(3584.5,412.5) v1(3584.5,472.5)
  Bottom Layer w40: v1(3584.5,412.5) v1(3584.5,472.5)
NetD10_1: D10.1 R34.2 | length 73.3
  Top Layer w10: R34.2@2971.5,160 2971.5,138.5 2979.53,130.47 D10.1@2979.53,90
NetD11_1: D11.1 R49.2 | length 108.1
  Top Layer w20: D11.1@199.53,750 257.01,750 v1(258.5,748.5)
  Bottom Layer w20: R49.2@258.5,700 v1(258.5,748.5)
NetD11_2: D11.2 Q6.3 | length 94
  Top Layer w20: v1(110,720) 110.47,720 D11.2@140.47,750
  Bottom Layer w20: v1(110,720) 157.24,720 Q6.3@160,717.24
NetD12_1: D12.1 R50.2 | length 107.3
  Top Layer w10: v1(4160,760) D12.1@4200.47,760
  Bottom Layer w10: R50.2@4101.5,740 4140,740 v1(4160,760)
NetD12_2: D12.2 Q7.3 | length 134.8
  Top Layer w10: D12.2@4259.53,760 v1(4300,760)
  Bottom Layer w10: Q7.3@4260,682.24 4300,722.24 v1(4300,760)
NetF1_2: F1.2 J1.1 TP1.1 | length 950
  Top Layer w140: J1.1@160,1500 TP1.1@160,1710 ; TP1.1@180,1710 290,1710
  Signal Layer 1 w130: J1.1@160,1500 TP1.1@160,1710
  Signal Layer 2 w130: J1.1@160,1500 TP1.1@160,1710
  Bottom Layer w130: J1.1@160,1500 TP1.1@160,1710
NetF2_1: F2.1 J3.2 TP4.1 | length 980
  Top Layer w130: F2.1@4100,1710 TP4.1@4240,1710 J3.2@4240,1500
  Signal Layer 1 w130: J3.2@4240,1500 TP4.1@4240,1710
  Signal Layer 2 w130: J3.2@4240,1500 TP4.1@4240,1710
  Bottom Layer w130: J3.2@4240,1500 TP4.1@4240,1710
NetJ1_2: J1.2 R13.1 R17.1 TP12.1 | length 2457.1
  Top Layer w10: 243.86,895 v2(370,895)
  Top Layer w140: 160,905 TP12.1@160,1040 J1.2@160,1300
  Signal Layer 1 w120: TP12.1@160,1040 J1.2@160,1300
  Signal Layer 2 w120: TP12.1@160,1040 J1.2@160,1300
  Bottom Layer w10: v2(370,895) 395,920 1055.28,920 1177.4,797.87 1252.6,797.87 1305.72,851 1399,851 1410,840 R17.1@1410,811.5
  Bottom Layer w120: TP12.1@160,1040 J1.2@160,1300
NetJ3_1: J3.1 R14.2 R18.1 TP11.1 | length 1885.4
  Top Layer w10: v2(3721,800) R14.2@3781.14,800
  Top Layer w120: TP11.1@4240,1050 J3.1@4240,1300
  Signal Layer 1 w120: TP11.1@4240,1050 J3.1@4240,1300
  Signal Layer 2 w120: TP11.1@4240,1050 J3.1@4240,1300
  Bottom Layer w10: R18.1@2980,811.5 2980,815 3010,845 3130,845 3235,740 3530,740 3545,755 3676,755 v2(3721,800)
  Bottom Layer w120: TP11.1@4240,1050 J3.1@4240,1300
NetJ5_2: J5.2 R40.2 | length 152
  Bottom Layer w10: R40.2@2598.5,190 2598.5,181.5 J5.2@2700,80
